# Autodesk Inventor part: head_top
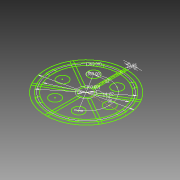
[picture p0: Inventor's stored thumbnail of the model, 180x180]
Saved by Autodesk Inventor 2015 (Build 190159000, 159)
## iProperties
Created: 2017-06
Part Number: head_top
Material: Generic
Document SubType Name: Modeling
Designer: mcalderon
Density: 1 g/cm^3
Appearance: Default
Author: mcalderon
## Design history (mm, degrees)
sketch "Sketch1" dims "d0" = 90, "d17" = 74
  geometry: L1 (1.475, 44.476)-(-1.475, 44.476); L2 (-4, 36.5)-(4, 40.5); L3 (4, 36.5)-(-4, 40.5); L4 (0, 44)-(0, 8.5); L5 (-1.475, 8.024)-(1.475, 8.024); L6 (1.475, 8.024)-(1.475, 44.476); L7 (1.475, 44.476)-(-1.475, 44.476); L8 (-1.475, 44.476)-(-1.475, 8.024); L9 (-1.475, 8.024)-(1.475, 44.476); L10 (1.475, 8.024)-(-1.475, 44.476); L11 (-8.12, 2.485)-(-6.645, 5.039); L12 (-39.688, 20.711)-(-8.12, 2.485); L13 (-6.645, 5.039)-(-38.213, 23.265); L14 (-6.645, -6.039)-(-8.12, -3.485); L15 (-38.213, -24.265)-(-6.645, -6.039); L16 (-8.12, -3.485)-(-39.688, -21.711); L17 (1.475, -9.024)-(-1.475, -9.024); L18 (1.475, -45.476)-(1.475, -9.024); L19 (-1.475, -9.024)-(-1.475, -45.476); L20 (8.12, -3.485)-(6.645, -6.039); L21 (39.688, -21.711)-(8.12, -3.485); L22 (6.645, -6.039)-(38.213, -24.265); L23 (6.645, 5.039)-(8.12, 2.485); L24 (38.213, 23.265)-(6.645, 5.039); L25 (8.12, 2.485)-(39.688, 20.711); L26 (0, -0.5)-(45, -0.5); L27 (-16.036, 35.275)-(-17.146, 37.194); L28 (-22.964, 31.275)-(-24.071, 33.195); L29 (-22.964, 31.275)-(-21.854, 29.356); L30 (-16.036, 35.275)-(-14.929, 33.355); L31 (-24.071, 33.195)-(-17.146, 37.194); L32 (-21.854, 29.356)-(-14.929, 33.355); L33 (-39, -4.5)-(-41.217, -4.498); L34 (-39, -4.5)-(-36.783, -4.498); L35 (-36.783, -4.498)-(-36.783, 3.498); L36 (-39, 3.5)-(-36.783, 3.498); L37 (-39, 3.5)-(-41.217, 3.498); L38 (-41.217, -4.498)-(-41.217, 3.498); L39 (-16.036, -36.275)-(-17.146, -38.194); L40 (-16.036, -36.275)-(-14.929, -34.355); L41 (-14.929, -34.355)-(-21.854, -30.356); L42 (-22.964, -32.275)-(-21.854, -30.356); L43 (-22.964, -32.275)-(-24.071, -34.195); L44 (-17.146, -38.194)-(-24.071, -34.195); L45 (22.964, -32.275)-(24.071, -34.195); L46 (22.964, -32.275)-(21.854, -30.356); L47 (21.854, -30.356)-(14.929, -34.355); L48 (16.036, -36.275)-(14.929, -34.355); L49 (16.036, -36.275)-(17.146, -38.194); L50 (24.071, -34.195)-(17.146, -38.194); L51 (39, 3.5)-(41.217, 3.498); L52 (39, 3.5)-(36.783, 3.498); L53 (36.783, 3.498)-(36.783, -4.498); L54 (39, -4.5)-(36.783, -4.498); L55 (39, -4.5)-(41.217, -4.498); L56 (41.217, 3.498)-(41.217, -4.498); L57 (16.036, 35.275)-(17.146, 37.194); L58 (16.036, 35.275)-(14.929, 33.355); L59 (14.929, 33.355)-(21.854, 29.356); L60 (22.964, 31.275)-(21.854, 29.356); L61 (22.964, 31.275)-(24.071, 33.195); L62 (17.146, 37.194)-(24.071, 33.195); C1 r 41 at (0, -0.5); C2 r 7 at (0, -0.5); C3 r 6 at (-13.518, 21.464); C4 r 6 at (-25.78, -1.225); C5 r 6 at (-12.262, -23.189); C6 r 6 at (13.518, -22.464); C7 r 6 at (25.78, 0.225); C8 r 6 at (12.262, 22.189); 4 further points
  constraints: 124 end point, 8 centre point, 5 midpoint, 3 coincident, 2 horizontal, 2 parallel, 1 perpendicular, 1 vertical, 135 other
  dimensions: "d2" = 2.95 distance of L1.end L1.start; "d16" = 82 diameter of C1; "d19" = 14 diameter of C2; "d25" = 2.95 distance of L7.end L1.start; "d26" = 12 diameter of C3; "d29" = 360 deg dimension on point (0, -0.5) C3.centre (derived); "d33" = 360 deg dimension on point (0, -0.5) L5.start (derived); "d39" = 360 deg dimension on point (0, -0.5) L28.start (derived)
